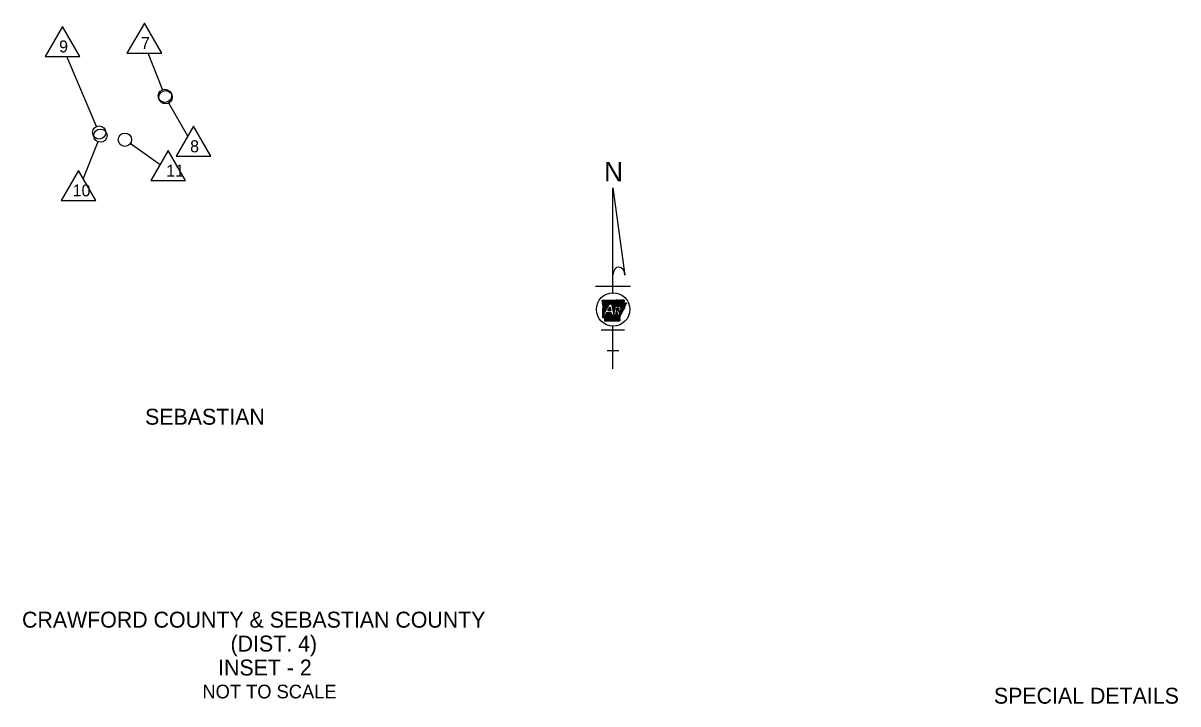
# Model space of a CAD drawing. Extents: x -17668 to 16999, y -17303 to 5867.
# Drawn here: x 8192 to 16879, y -4303 to 820 of the extents above; entities that cross this region are included whole.
import ezdxf

# ---------------------------------------------------------------- set-up
doc = ezdxf.new("R2010")
doc.units = 0
doc.layers.add('2', color=7, linetype='Continuous')
doc.layers.add('48', color=7, linetype='Continuous')

msp = doc.modelspace()

# ---------------------------------------------------------------- linework, layer by layer
at = {"layer": '48'}
for p, q in [((8488.9, 795.2), (8358.3, 569)), ((8619.6, 569), (8488.9, 795.2)), ((9104.3, 820.1), (8973.7, 593.9)), ((9234.9, 593.9), (9104.3, 820.1)), ((8358.3, 569), (8619.6, 569)), ((8744.9, 43), (8521, 569)), ((8973.7, 593.9), (9234.9, 593.9)), ((9241.1, 319.7), (9133.8, 593.9)), ((9430.9, -30.7), (9288.9, 218.7)), ((9474.1, 44.2), (9343.5, -182)), ((9604.7, -182), (9474.1, 44.2)), ((8755.1, -73.2), (8644.8, -349.5)), ((9222.2, -246.2), (8998.6, -86.2)), ((9283.9, -139.2), (9153.3, -365.4)), ((9414.5, -365.4), (9283.9, -139.2)), ((9343.5, -182), (9604.7, -182)), ((8609.2, -287.9), (8478.6, -514.1)), ((8739.8, -514.1), (8609.2, -287.9)), ((9153.3, -365.4), (9414.5, -365.4)), ((12628.6, -420.4), (12719.6, -1077.5)), ((12628.6, -1208.3), (12628.6, -420.4)), ((8478.6, -514.1), (8739.8, -514.1)), ((12497, -1159.6), (12760.2, -1159.6)), ((12548.8, -1264.8), (12549.9, -1263.7)), ((12549.2, -1267.9), (12553.4, -1263.7)), ((12549.6, -1271), (12556.9, -1263.7)), ((12550, -1274.1), (12560.3, -1263.7)), ((12550.3, -1277.2), (12563.8, -1263.7)), ((12550.7, -1280.3), (12567.3, -1263.7)), ((12551.1, -1283.4), (12570.8, -1263.7)), ((12551.5, -1286.5), (12574.3, -1263.7)), ((12551.9, -1289.6), (12577.7, -1263.7)), ((12552.3, -1292.7), (12581.2, -1263.7)), ((12552.7, -1295.7), (12584.7, -1263.7)), ((12553, -1298.8), (12588.2, -1263.7)), ((12553.4, -1301.9), (12591.7, -1263.7)), ((12553.8, -1305), (12595.1, -1263.7)), ((12553.8, -1343.4), (12600.8, -1296.4)), ((12553.9, -1339.8), (12630, -1263.7)), ((12554.1, -1336.1), (12626.5, -1263.7)), ((12554.2, -1332.5), (12623.1, -1263.7)), ((12554.2, -1308.1), (12598.6, -1263.7)), ((12554.3, -1328.9), (12619.6, -1263.7)), ((12554.4, -1325.3), (12616.1, -1263.7)), ((12554.5, -1321.7), (12612.6, -1263.7)), ((12554.6, -1311.2), (12602.1, -1263.7)), ((12554.7, -1318.1), (12609.1, -1263.7)), ((12554.8, -1314.5), (12605.6, -1263.7)), ((12555, -1377.3), (12603.6, -1291.5)), ((12603.6, -1291.5), (12618, -1291.5)), ((12605.7, -1291.5), (12633.5, -1263.6)), ((12609.1, -1291.5), (12637, -1263.6)), ((12612.6, -1291.5), (12640.5, -1263.6)), ((12616.1, -1291.5), (12644.1, -1263.6)), ((12618.3, -1292.8), (12647.6, -1263.5)), ((12618.9, -1295.7), (12651.1, -1263.4)), ((12619.5, -1298.6), (12654.7, -1263.4)), ((12620.1, -1301.4), (12658.2, -1263.3)), ((12620.7, -1304.3), (12661.8, -1263.3)), ((12621.3, -1307.2), (12665.3, -1263.2)), ((12622, -1310), (12668.8, -1263.2)), ((12622.6, -1312.9), (12672.4, -1263.1)), ((12623.2, -1315.8), (12675.9, -1263.1)), ((12623.8, -1318.6), (12679.4, -1263)), ((12624.4, -1321.5), (12683, -1262.9)), ((12625, -1324.4), (12686.5, -1262.9)), ((12625.6, -1327.3), (12690.1, -1262.8)), ((12626.3, -1330.1), (12693.6, -1262.7)), ((12650.5, -1309.4), (12697.2, -1262.7)), ((12653.9, -1309.4), (12700.8, -1262.6)), ((12657.4, -1309.4), (12704.3, -1262.5)), ((12660.9, -1309.4), (12707.9, -1262.4)), ((12664.4, -1309.4), (12711.5, -1262.3)), ((12667.9, -1309.4), (12712.2, -1265)), ((12671.3, -1309.4), (12713.9, -1266.8)), ((12674.8, -1309.4), (12714.4, -1269.9)), ((12678.3, -1309.4), (12706.4, -1281.3)), ((12681.5, -1309.7), (12705.7, -1285.5)), ((12683.4, -1311.3), (12709.4, -1285.3)), ((12685.1, -1313.1), (12713.1, -1285.1)), ((12686.6, -1315.1), (12716.8, -1284.9)), ((12687.9, -1317.3), (12720.4, -1284.7)), ((12688.9, -1319.7), (12724.1, -1284.5)), ((12689.5, -1333.1), (12721.1, -1301.4)), ((12689.7, -1322.4), (12727.4, -1284.7)), ((12690.2, -1325.4), (12729, -1286.6)), ((12690.2, -1328.8), (12720.7, -1298.4)), ((12727.5, -1291.6), (12730.7, -1288.4)), ((12552.2, -1393.7), (12568.6, -1377.3)), ((12552.3, -1390.2), (12565.1, -1377.3)), ((12552.4, -1386.6), (12561.7, -1377.3)), ((12552.5, -1383), (12558.2, -1377.3)), ((12552.6, -1379.4), (12555.3, -1376.7)), ((12552.7, -1375.8), (12559.9, -1368.6)), ((12552.9, -1372.2), (12564.4, -1360.6)), ((12553, -1368.6), (12569, -1352.6)), ((12553.1, -1365), (12573.5, -1344.5)), ((12553.2, -1361.4), (12578.1, -1336.5)), ((12553.3, -1357.8), (12582.6, -1328.5)), ((12553.5, -1354.2), (12587.2, -1320.4)), ((12553.5, -1395.9), (12590.1, -1359.3)), ((12553.6, -1350.6), (12591.7, -1312.4)), ((12553.7, -1347), (12596.3, -1304.4)), ((12571.6, -1377.3), (12555, -1377.3)), ((12555.6, -1397.3), (12593.6, -1359.3)), ((12558.1, -1398.3), (12597.1, -1359.3)), ((12562.2, -1397.7), (12600.6, -1359.3)), ((12565.7, -1397.6), (12604, -1359.3)), ((12568.5, -1398.4), (12607.5, -1359.3)), ((12568.6, -1405.2), (12614.5, -1359.3)), ((12568.6, -1401.7), (12611, -1359.3)), ((12568.6, -1408.7), (12616.3, -1361)), ((12568.6, -1412.1), (12616.9, -1363.8)), ((12568.6, -1415.6), (12617.5, -1366.7)), ((12568.6, -1419.1), (12618.2, -1369.6)), ((12568.7, -1422.5), (12618.8, -1372.4)), ((12581.8, -1359.3), (12571.6, -1377.3)), ((12572.2, -1422.5), (12619.4, -1375.3)), ((12575.6, -1370.3), (12586.6, -1359.3)), ((12575.6, -1422.5), (12620.9, -1377.3)), ((12579.1, -1422.5), (12624.3, -1377.3)), ((12580.1, -1362.3), (12583.1, -1359.3)), ((12616, -1359.3), (12581.8, -1359.3)), ((12582.6, -1422.5), (12627.8, -1377.3)), ((12586.1, -1422.5), (12631.3, -1377.3)), ((12589.6, -1422.6), (12634.8, -1377.3)), ((12590.7, -1343.6), (12606.6, -1315.6)), ((12590.7, -1343.6), (12612.6, -1343.6)), ((12590.9, -1343.6), (12608.8, -1325.7)), ((12593, -1422.6), (12638.3, -1377.3)), ((12594.4, -1343.6), (12609.4, -1328.6)), ((12595, -1336), (12608.2, -1322.9)), ((12596.5, -1422.6), (12641.8, -1377.3)), ((12597.8, -1343.6), (12610, -1331.5)), ((12599.6, -1328), (12607.6, -1320)), ((12600, -1422.6), (12645.2, -1377.3)), ((12601.3, -1343.6), (12610.6, -1334.3)), ((12603.5, -1422.6), (12663.4, -1362.7)), ((12604.1, -1319.9), (12606.9, -1317.1)), ((12604.8, -1343.6), (12611.2, -1337.2)), ((12606.9, -1422.6), (12664.3, -1365.2)), ((12608.3, -1343.6), (12611.8, -1340.1)), ((12610.4, -1422.6), (12665.2, -1367.8)), ((12611.8, -1343.6), (12612.5, -1343)), ((12613.9, -1422.6), (12666.2, -1370.3)), ((12617.4, -1422.6), (12667.1, -1372.8)), ((12648.1, -1377.3), (12619.8, -1377.3)), ((12620.8, -1422.6), (12668.1, -1375.4)), ((12624.3, -1422.6), (12669.6, -1377.3)), ((12626.9, -1333), (12646.6, -1313.2)), ((12627.5, -1335.9), (12645.9, -1317.4)), ((12627.8, -1422.6), (12673.1, -1377.3)), ((12628.1, -1338.7), (12645.2, -1321.7)), ((12628.7, -1341.6), (12644.4, -1325.9)), ((12629.3, -1344.5), (12643.7, -1330.1)), ((12629.9, -1347.3), (12643, -1334.3)), ((12630.6, -1350.2), (12642.2, -1338.5)), ((12631.2, -1353.1), (12641.5, -1342.8)), ((12631.3, -1422.6), (12676.6, -1377.3)), ((12631.8, -1355.9), (12640.8, -1347)), ((12632.4, -1358.8), (12640, -1351.2)), ((12633, -1361.7), (12639.3, -1355.4)), ((12633.6, -1364.6), (12638.5, -1359.6)), ((12634.2, -1367.4), (12637.8, -1363.8)), ((12634.8, -1422.6), (12680.1, -1377.3)), ((12634.9, -1370.3), (12637.1, -1368.1)), ((12635.5, -1373.2), (12636.3, -1372.3)), ((12638.2, -1422.6), (12681.2, -1379.6)), ((12641.7, -1422.6), (12681.4, -1383)), ((12645.2, -1422.6), (12681.5, -1386.3)), ((12647.3, -1309.4), (12681, -1309.4)), ((12648.7, -1373.9), (12662.4, -1360.1)), ((12648.7, -1422.6), (12681.7, -1389.6)), ((12649.4, -1369.6), (12661.5, -1357.6)), ((12650.2, -1365.4), (12660.5, -1355)), ((12650.9, -1361.2), (12659.6, -1352.5)), ((12651.6, -1357), (12658.6, -1350)), ((12652.4, -1352.8), (12655.1, -1350)), ((12658.7, -1350), (12652.8, -1350)), ((12654.6, -1339.8), (12673, -1321.5)), ((12654.6, -1339.8), (12669.1, -1339.8)), ((12655.4, -1335.7), (12669.5, -1321.5)), ((12656.1, -1331.4), (12666, -1321.5)), ((12656.8, -1327.2), (12662.5, -1321.5)), ((12657.6, -1323), (12659, -1321.5)), ((12657.8, -1321.5), (12673.7, -1321.5)), ((12658.1, -1339.8), (12674.9, -1323.1)), ((12668.8, -1377.3), (12658.7, -1350)), ((12661.6, -1339.8), (12676.1, -1325.4)), ((12665.1, -1339.8), (12676.7, -1328.2)), ((12668.6, -1339.8), (12676.4, -1332)), ((12683.6, -1377.3), (12668.8, -1377.3)), ((12673, -1348.6), (12683.6, -1377.3)), ((12673.2, -1349.3), (12674.3, -1348.2)), ((12674.2, -1351.8), (12680.8, -1345.2)), ((12675.1, -1354.4), (12713.7, -1315.8)), ((12676.1, -1356.9), (12714.4, -1318.6)), ((12677, -1359.5), (12715, -1321.4)), ((12677.9, -1362), (12715.7, -1324.3)), ((12678.9, -1364.6), (12699.8, -1343.7)), ((12679.8, -1367.1), (12699.4, -1347.5)), ((12680.8, -1369.7), (12699, -1351.4)), ((12681.7, -1372.2), (12692.4, -1361.5)), ((12682.6, -1374.7), (12690.9, -1366.5)), ((12686.5, -1339.6), (12713.1, -1313)), ((12703.8, -1339.7), (12708.7, -1334.8)), ((12717.2, -1308.8), (12721.5, -1304.5)), ((12628.6, -1780.2), (12628.6, -1460.4)), ((12652.1, -1422.7), (12676, -1398.8)), ((12655.6, -1422.7), (12677.1, -1401.2)), ((12659.1, -1422.7), (12678.1, -1403.6)), ((12662.6, -1422.7), (12679.2, -1406)), ((12666.1, -1422.7), (12680.3, -1408.4)), ((12669.5, -1422.7), (12681.2, -1411)), ((12673, -1422.7), (12679.6, -1416.1)), ((12676.5, -1422.7), (12678, -1421.1)), ((12540.9, -1487.6), (12716.3, -1487.6)), ((12584.8, -1643.4), (12672.5, -1643.4))]:
    msp.add_line(p, q, dxfattribs=at)
for points in [[(12548.7, -1263.7), (12596.7, -1263.7), (12638.9, -1263.6), (12688.6, -1262.9), (12711.7, -1262.3)], [(12548.7, -1263.7), (12596.7, -1263.7), (12638.9, -1263.6), (12688.6, -1262.9), (12711.7, -1262.3)], [(12554, -1338.4), (12554.8, -1313.1), (12548.7, -1263.7)], [(12552.1, -1393.7), (12554.8, -1313.1), (12548.7, -1263.7)], [(12618, -1291.5), (12635.9, -1375), (12647.3, -1309.4)], [(12726.8, -1284.4), (12730.9, -1288.7), (12720.6, -1297.3), (12721.7, -1305.9), (12712.8, -1311.7), (12715.8, -1325), (12709, -1331.2), (12708.4, -1338), (12700, -1341), (12698.8, -1353.8), (12692.8, -1360.2), (12689.9, -1369.9), (12681.2, -1377.9), (12681.8, -1392), (12675.9, -1398.6), (12681.3, -1410.7), (12677.5, -1422.7)], [(12704.6, -1285.5), (12727.1, -1284.4)], [(12704.6, -1285.5), (12727.1, -1284.4)], [(12552.2, -1393.7), (12554, -1338.4)], [(12606.6, -1315.6), (12612.6, -1343.6)], [(12619.8, -1377.3), (12616, -1359.3)], [(12652.8, -1350), (12648.1, -1377.3)], [(12654.6, -1339.8), (12657.8, -1321.5)], [(12677.5, -1422.7), (12568.6, -1422.5), (12568.6, -1398.5)], [(12677.5, -1422.7), (12568.6, -1422.5), (12568.6, -1398.5)]]:
    msp.add_lwpolyline(points, dxfattribs=at)
for centre in [(9259.3, 273.1), (9264.2, 262.2), (8764.5, -3), (8773.6, -26.8), (8957.9, -57.2)]:
    msp.add_circle(centre, 50, dxfattribs=at)
for centre, major_axis, ratio, start_param, end_param in [((12674.1, -1078.9), (-1.9, 63.2), 0.719778, 4.712385, 7.768526), ((12665.6, -1329.3), (-11.1, 0), 0.999987, 1.887169, 3.90762), ((12668.5, -1327.2), (-21.8, 0), 0.999987, 1.777838, 4.099264)]:
    msp.add_ellipse(centre, major_axis=major_axis, ratio=ratio, start_param=start_param, end_param=end_param, dxfattribs=at)
msp.add_ellipse((12630.7, -1334.4), major_axis=(126, 0), ratio=0.999976, dxfattribs=at)
for points in [[(12711.7, -1262.3), (12711.8, -1263.6), (12712.2, -1264.3), (12712.3, -1265.6), (12712.8, -1266.1), (12713.7, -1266.6), (12714.4, -1267.5), (12714.6, -1268.5), (12714.4, -1269.5), (12714.3, -1270.7), (12714.2, -1271.7), (12714, -1272.6), (12713.3, -1273.4), (12712.6, -1273.9), (12712, -1274.5), (12711.6, -1275.2), (12710.8, -1275.9), (12710, -1276.7), (12709.4, -1277.3), (12708.8, -1278.1), (12708.5, -1279), (12707.8, -1279.7), (12707.3, -1280.3), (12706.5, -1281.1), (12706.2, -1281.9), (12705.5, -1282.8), (12705.4, -1283.7), (12704.9, -1284.4), (12704.9, -1284.6)], [(12711.7, -1262.3), (12711.8, -1263.6), (12712.3, -1264.3), (12712.3, -1265.6), (12712.8, -1266.1), (12713.7, -1266.6), (12714.5, -1267.5), (12714.6, -1268.5), (12714.4, -1269.5), (12714.3, -1270.7), (12714.2, -1271.7), (12714, -1272.6), (12713.3, -1273.4), (12712.6, -1273.9), (12712, -1274.5), (12711.6, -1275.2), (12710.8, -1275.9), (12710, -1276.6), (12709.4, -1277.3), (12708.8, -1278.1), (12708.5, -1279.1), (12707.8, -1279.7), (12707.3, -1280.3), (12706.5, -1281.1), (12706.2, -1281.9), (12705.5, -1282.8), (12705.4, -1283.7), (12704.9, -1284.4), (12704.9, -1284.6)], [(12726.8, -1284.4), (12727.1, -1284.4), (12728.1, -1285.4), (12728.6, -1286.3), (12729.2, -1286.8), (12730, -1287.1), (12730.5, -1287.8), (12730.9, -1288.5), (12730.7, -1289.2), (12729.9, -1289.3), (12728.9, -1289.4), (12728.1, -1289.4), (12727.3, -1290), (12728, -1290.8), (12728.9, -1291.5), (12729.1, -1292.3), (12728.6, -1293.1), (12727.7, -1293.5), (12726.7, -1293.9), (12725.9, -1294.6), (12725.5, -1295.3), (12724.6, -1295.5), (12723.7, -1295.8), (12722.8, -1295.9), (12721.9, -1296.1), (12721, -1296.5), (12720.6, -1297.3), (12720.7, -1298.4), (12720.7, -1299.6), (12721.6, -1299.9), (12722.5, -1300), (12723.4, -1300.4), (12723.2, -1301.1), (12722.6, -1301.9), (12721.9, -1302.6), (12721.1, -1302.9), (12720.5, -1303.5), (12720.7, -1304.1), (12721.3, -1304.5), (12721.8, -1305.2), (12721.7, -1305.8), (12721, -1306.3), (12720.2, -1306.1), (12719.6, -1305.4), (12719, -1305.2), (12718.4, -1304.9), (12717.8, -1305.3), (12717.8, -1306.1), (12717.5, -1307), (12717.8, -1307.7), (12718, -1308.7), (12718, -1309.4), (12717.8, -1310.4), (12717.2, -1311.5), (12716.7, -1311.8), (12716.4, -1310.6), (12716.3, -1309.7), (12715.9, -1309.2), (12715.5, -1309.2), (12714.8, -1309.6), (12714.2, -1310.3), (12713.3, -1311), (12712.8, -1311.8), (12713.1, -1312.7), (12713.7, -1312.9), (12714.2, -1312.8), (12714.5, -1312.2), (12715, -1312.1), (12715.5, -1313)], [(12682.1, -1381.7), (12681.8, -1382.4), (12681.5, -1383.6), (12681.6, -1384.6), (12682, -1385.5), (12682.7, -1386), (12683.5, -1386.6), (12683.4, -1387.7), (12683, -1388.1), (12681.9, -1387.8), (12681.1, -1387.4), (12680.5, -1387.7), (12679.6, -1388.1), (12678.9, -1388.2), (12678.9, -1389.6), (12679.8, -1390.6), (12680.6, -1390.6), (12681.5, -1390.8), (12681.9, -1391.8), (12681.3, -1392.7), (12680.4, -1393.2), (12679.3, -1392.6), (12678.5, -1392.1), (12677.7, -1391.5), (12676.7, -1391.3), (12676.1, -1391.4), (12675.8, -1392.6), (12676.3, -1393.7), (12677.1, -1394.5), (12677.8, -1395.5), (12677.7, -1396.3), (12677.2, -1396.5), (12676.2, -1396.7), (12675.6, -1397), (12675.5, -1397.2), (12675.8, -1398.2), (12676.1, -1399.3), (12676.1, -1400.2), (12675.7, -1400.9), (12675.2, -1402.1), (12675.3, -1402.9), (12675.6, -1403.3), (12676.1, -1403.1), (12676.7, -1402.7), (12677.1, -1402.2), (12677.4, -1401.7), (12678, -1401.2), (12678.8, -1401.6), (12679, -1402.5), (12678.5, -1403.3), (12677.9, -1403.7), (12677.1, -1404), (12676.6, -1404.6), (12676.7, -1405.4), (12677.2, -1405.8), (12678.3, -1405.6), (12679, -1405.3), (12679.4, -1404.9), (12679.9, -1404.4), (12680.2, -1403.8), (12680.6, -1403.3), (12681.3, -1403.2), (12681.6, -1403.6), (12681.5, -1404.6), (12681.1, -1405.6), (12680.5, -1406.4), (12679.9, -1406.9), (12679.1, -1408.2), (12679.2, -1409.3), (12679.6, -1410.2), (12679.9, -1410.9), (12680.7, -1410.8), (12681.5, -1410.7), (12681.9, -1411.1), (12681.9, -1411.9), (12681.3, -1412.7), (12680.7, -1413.5), (12680.4, -1414.5), (12680.6, -1415.3), (12680.6, -1416), (12680.3, -1416.7), (12679.9, -1417.1), (12678.8, -1417.1), (12677.6, -1417), (12677, -1417.4), (12677.1, -1418.4), (12677.8, -1419.1), (12678.3, -1419.5), (12679, -1420.3), (12679.3, -1421), (12679.2, -1421.6), (12678.7, -1422.1), (12677.5, -1422.7)], [(12682.1, -1381.7), (12681.8, -1382.4), (12681.5, -1383.6), (12681.6, -1384.6), (12682, -1385.5), (12682.7, -1386), (12683.5, -1386.6), (12683.4, -1387.7), (12683, -1388.1), (12681.9, -1387.8), (12681.1, -1387.4), (12680.5, -1387.7), (12679.6, -1388.1), (12678.9, -1388.2), (12678.9, -1389.6), (12679.8, -1390.6), (12680.6, -1390.6), (12681.5, -1390.8), (12681.9, -1391.8), (12681.3, -1392.7), (12680.4, -1393.2), (12679.3, -1392.6), (12678.5, -1392.1), (12677.7, -1391.5), (12676.7, -1391.3), (12676.1, -1391.4), (12675.8, -1392.6), (12676.3, -1393.7), (12677.1, -1394.5), (12677.8, -1395.5), (12677.7, -1396.3), (12677.2, -1396.5), (12676.2, -1396.7), (12675.6, -1397), (12675.5, -1397.2), (12675.8, -1398.2), (12676.1, -1399.3), (12676.1, -1400.2), (12675.7, -1400.9), (12675.2, -1402.1), (12675.3, -1402.9), (12675.6, -1403.3), (12676.1, -1403.1), (12676.7, -1402.7), (12677.1, -1402.2), (12677.4, -1401.7), (12678, -1401.2), (12678.8, -1401.6), (12679, -1402.5), (12678.5, -1403.3), (12677.9, -1403.7), (12677.1, -1404), (12676.6, -1404.6), (12676.7, -1405.4), (12677.2, -1405.8), (12678.3, -1405.6), (12679, -1405.3), (12679.4, -1404.9), (12679.9, -1404.4), (12680.2, -1403.8), (12680.6, -1403.3), (12681.3, -1403.2), (12681.6, -1403.6), (12681.5, -1404.6), (12681.1, -1405.6), (12680.5, -1406.4), (12679.9, -1406.9), (12679.1, -1408.2), (12679.2, -1409.3), (12679.6, -1410.2), (12679.9, -1410.9), (12680.7, -1410.8), (12681.5, -1410.7), (12681.9, -1411.1), (12681.9, -1411.9), (12681.3, -1412.7), (12680.7, -1413.5), (12680.4, -1414.5), (12680.6, -1415.3), (12680.6, -1416), (12680.3, -1416.7), (12679.9, -1417.1), (12678.8, -1417.1), (12677.6, -1417), (12677, -1417.4), (12677.1, -1418.4), (12677.8, -1419.1), (12678.3, -1419.5), (12679, -1420.3), (12679.3, -1421), (12679.2, -1421.6), (12678.7, -1422.1), (12677.5, -1422.7)], [(12686.1, -1370.6), (12686, -1370.6), (12685.5, -1371.3), (12685.8, -1372.3), (12686.9, -1372.7), (12687.5, -1373.7), (12687.5, -1374.6), (12687.1, -1375.9), (12686.6, -1376.4), (12685.5, -1376.7), (12684.7, -1376.8), (12684.6, -1378.2), (12684.3, -1378.9), (12683.6, -1379.1), (12682.7, -1378.6), (12682.2, -1378.4), (12681.6, -1378.1), (12680.7, -1377.6), (12680.1, -1377.7), (12680.3, -1379), (12680.3, -1379.1), (12681.1, -1380.1), (12681.7, -1380.8), (12682.1, -1381.7)], [(12686.1, -1370.6), (12686, -1370.6), (12685.5, -1371.3), (12685.8, -1372.3), (12686.9, -1372.7), (12687.5, -1373.7), (12687.5, -1374.6), (12687.1, -1375.9), (12686.6, -1376.4), (12685.5, -1376.7), (12684.7, -1376.8), (12684.6, -1378.2), (12684.3, -1378.9), (12683.6, -1379.1), (12682.7, -1378.6), (12682.2, -1378.4), (12681.6, -1378.1), (12680.7, -1377.6), (12680.1, -1377.7), (12680.3, -1379), (12680.3, -1379.1), (12681.1, -1380.1), (12681.7, -1380.8), (12682.1, -1381.7)], [(12702.6, -1342.4), (12701.5, -1343.2), (12701.1, -1344.1), (12698.4, -1343.8), (12698.5, -1344.7), (12697.5, -1345.2), (12696.7, -1345.8), (12697.2, -1346.6), (12698.1, -1347.2), (12699, -1347.7), (12699.5, -1348.2), (12699.7, -1349.4), (12699.8, -1350.2), (12700.1, -1351.3), (12700.3, -1352), (12699.7, -1352.9), (12699.1, -1353.1), (12698.4, -1352.9), (12697.7, -1352.8), (12697.1, -1353.4), (12696.6, -1354.2), (12696.2, -1355.1), (12695.8, -1355.8), (12695.5, -1356.6), (12694.9, -1357.5), (12694.1, -1357.6), (12693.1, -1357.8), (12692.5, -1358.5), (12692.6, -1359.6), (12693.2, -1360.3), (12693.6, -1361.3), (12693.9, -1362.1), (12693.7, -1363.1), (12693.3, -1363.8), (12692.8, -1364.3), (12692.5, -1365.2), (12692.1, -1365.9), (12691.8, -1366.2), (12691.1, -1366.1), (12690.3, -1365.9), (12689.7, -1366), (12689, -1366.3), (12688.4, -1366.1), (12687.7, -1365.4), (12687.2, -1364.9), (12686.6, -1364.7), (12686, -1365), (12685.9, -1366), (12686.2, -1367), (12686.4, -1368.4), (12686.2, -1369.2), (12686.1, -1370.6)], [(12715.5, -1313), (12715.6, -1313.8), (12715.1, -1314.8), (12714.9, -1315.7), (12715, -1316.6), (12714, -1317.1), (12713.2, -1317.7), (12713.7, -1318.4), (12714.6, -1319.1), (12715.5, -1319.6), (12716, -1320.1), (12716.2, -1321.3), (12716.3, -1322.1), (12716.6, -1323.2), (12716.7, -1323.9), (12716.2, -1324.8), (12715.6, -1325), (12714.9, -1324.8), (12714.2, -1324.7), (12713.5, -1325.3), (12713.1, -1326.1), (12712.6, -1327), (12712.3, -1327.7), (12712, -1328.4), (12711.3, -1329.3), (12710.5, -1329.5), (12709.6, -1329.7), (12709, -1330.4), (12709.1, -1331.5), (12709.6, -1332.2), (12710.1, -1333.1), (12710.3, -1333.9), (12710.2, -1334.9), (12709.8, -1335.7), (12709.3, -1336.1), (12709, -1337.1), (12708.6, -1337.8), (12708.3, -1338), (12707.6, -1338), (12706.8, -1337.8), (12706.1, -1337.9), (12705.5, -1338.2), (12704.9, -1338), (12704.2, -1337.3), (12703.7, -1336.8), (12703.1, -1336.6), (12702.5, -1336.9), (12702.4, -1337.9), (12702.7, -1338.9), (12702.9, -1340.2), (12702.7, -1341.1), (12702.6, -1342.4)], [(12568.6, -1398.5), (12568.7, -1398.5), (12568.1, -1398.2), (12567.4, -1397.8), (12566.5, -1397.7), (12565.4, -1397.6), (12564.5, -1397.5), (12563.5, -1396.8), (12562.5, -1397.5), (12561.4, -1398), (12560.7, -1397.4), (12559.9, -1397.8), (12559.3, -1397.6), (12558.2, -1398.3), (12557.3, -1398.1), (12556.5, -1398.3), (12555.7, -1398.2), (12555.5, -1397.2), (12554.6, -1397.1), (12553.9, -1396.7), (12553.4, -1395.6), (12553, -1394.8), (12552.1, -1393.7)], [(12568.6, -1398.5), (12568.7, -1398.5), (12568.1, -1398.1), (12567.4, -1397.8), (12566.5, -1397.7), (12565.4, -1397.6), (12564.5, -1397.5), (12563.5, -1396.8), (12562.5, -1397.5), (12561.4, -1398), (12560.7, -1397.4), (12559.9, -1397.8), (12559.3, -1397.6), (12558.2, -1398.3), (12557.2, -1398.1), (12556.6, -1398.3), (12555.7, -1398.2), (12555.5, -1397.2), (12554.6, -1397.1), (12553.9, -1396.7), (12553.4, -1395.6), (12553, -1394.8), (12552.2, -1393.7)]]:
    msp.add_spline(points, degree=3, dxfattribs=at)

# ---------------------------------------------------------------- texts
at = {"layer": '2'}
msp.add_text('SEBASTIAN', height=120, dxfattribs=at).set_placement((9109.7, -2201.6))
at = {"layer": '48'}
for s, height, p in [('7', 90, (9078.8, 624.3)), ('9', 90, (8463.1, 599.4)), ('8', 90, (9448.6, -151.6)), ('11', 90, (9269.1, -335)), ('N', 146.7, (12563.3, -370.8)), ('10', 90, (8564.9, -483.7)), ('STS 10-03-17', 3.644, (12618.6, -1459.4)), ('CRAWFORD COUNTY & SEBASTIAN COUNTY', 120, (8184.2, -3728.7)), ('(DIST. 4)', 120, (9752.7, -3908.7)), ('INSET - 2', 120, (9659.1, -4088.7)), ('NOT TO SCALE', 102.885, (9541, -4260.8)), ('SPECIAL DETAILS', 120, (15494.9, -4300.8))]:
    msp.add_text(s, height=height, dxfattribs=at).set_placement(p)

doc.saveas('drawing.dxf')
